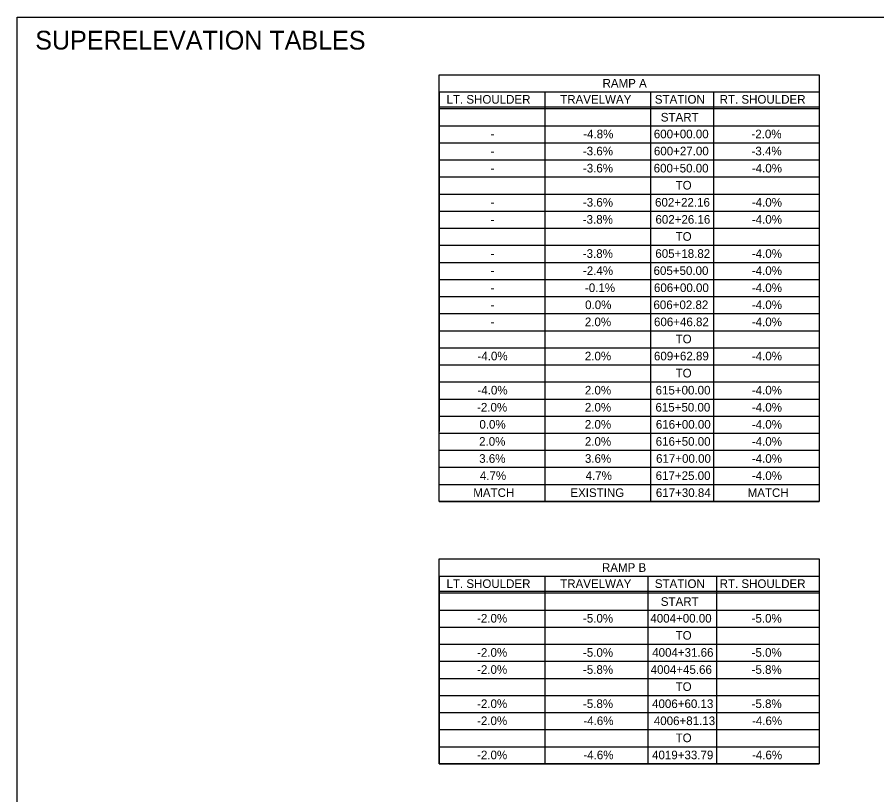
# Model space of a CAD drawing. Extents: x -15319374 to 1762012, y 465773 to 3693661.
# Drawn here: x -15314464.4 to -15314165.5, y 3691582.5 to 3691853 of the extents above; entities that cross this region are included whole.
import ezdxf

# ---------------------------------------------------------------- set-up
doc = ezdxf.new("R2010")
doc.units = 0
doc.layers.add('BORDER', color=7, linetype='Continuous')
doc.layers.add('DIMENSIONS', color=7, linetype='Continuous')

msp = doc.modelspace()

# ---------------------------------------------------------------- linework, layer by layer
at = {"layer": 'BORDER'}
for p, q in [((-15314317.7, 3691827.08), (-15314317.7, 3691708.88)), ((-15314280.93, 3691827.08), (-15314280.93, 3691702.35)), ((-15314244.16, 3691827.08), (-15314244.16, 3691702.35)), ((-15314222.29, 3691827.08), (-15314222.29, 3691702.35)), ((-15314185.52, 3691827.08), (-15314185.52, 3691702.35)), ((-15314317.7, 3691821.8), (-15314185.52, 3691821.8)), ((-15314317.7, 3691821.2), (-15314185.52, 3691821.2)), ((-15314317.7, 3691815.26), (-15314185.52, 3691815.26)), ((-15314317.7, 3691815.26), (-15314185.52, 3691815.26)), ((-15314317.7, 3691815.26), (-15314185.52, 3691815.26)), ((-15314317.7, 3691809.32), (-15314185.52, 3691809.32)), ((-15314317.7, 3691803.38), (-15314185.52, 3691803.38)), ((-15314317.7, 3691797.43), (-15314185.52, 3691797.43)), ((-15314317.7, 3691791.49), (-15314185.52, 3691791.49)), ((-15314317.7, 3691785.55), (-15314185.52, 3691785.55)), ((-15314317.7, 3691779.61), (-15314185.52, 3691779.61)), ((-15314317.7, 3691773.66), (-15314185.52, 3691773.66)), ((-15314317.7, 3691767.72), (-15314185.52, 3691767.72)), ((-15314317.7, 3691761.78), (-15314185.52, 3691761.78)), ((-15314317.7, 3691755.83), (-15314185.52, 3691755.83)), ((-15314317.7, 3691749.89), (-15314185.52, 3691749.89)), ((-15314317.7, 3691743.95), (-15314185.52, 3691743.95)), ((-15314317.7, 3691738.01), (-15314185.52, 3691738.01)), ((-15314317.7, 3691732.06), (-15314185.52, 3691732.06)), ((-15314317.7, 3691726.12), (-15314185.52, 3691726.12)), ((-15314317.7, 3691720.18), (-15314185.52, 3691720.18)), ((-15314317.7, 3691714.24), (-15314185.52, 3691714.24)), ((-15314317.7, 3691708.29), (-15314185.52, 3691708.29)), ((-15314317.7, 3691702.35), (-15314185.52, 3691702.35)), ((-15314280.93, 3691702.35), (-15314280.93, 3691684.52)), ((-15314244.16, 3691702.35), (-15314244.16, 3691684.52)), ((-15314222.29, 3691702.35), (-15314222.29, 3691684.52)), ((-15314317.7, 3691696.41), (-15314185.52, 3691696.41)), ((-15314317.7, 3691690.46), (-15314185.52, 3691690.46)), ((-15314317.7, 3691684.52), (-15314185.52, 3691684.52)), ((-15314317.7, 3691658.58), (-15314317.7, 3691593.28)), ((-15314280.93, 3691658.58), (-15314280.93, 3691593.28)), ((-15314245.16, 3691658.58), (-15314245.16, 3691593.28)), ((-15314221.29, 3691658.58), (-15314221.29, 3691593.28)), ((-15314185.52, 3691658.58), (-15314185.52, 3691593.28)), ((-15314317.7, 3691653.3), (-15314185.52, 3691653.3)), ((-15314317.7, 3691652.7), (-15314185.52, 3691652.7)), ((-15314317.7, 3691646.76), (-15314185.52, 3691646.76)), ((-15314317.7, 3691646.76), (-15314185.52, 3691646.76)), ((-15314317.7, 3691646.76), (-15314185.52, 3691646.76)), ((-15314317.7, 3691640.82), (-15314185.52, 3691640.82)), ((-15314317.7, 3691634.87), (-15314185.52, 3691634.87)), ((-15314317.7, 3691628.93), (-15314185.52, 3691628.93)), ((-15314317.7, 3691622.99), (-15314185.52, 3691622.99)), ((-15314317.7, 3691617.05), (-15314185.52, 3691617.05)), ((-15314317.7, 3691611.1), (-15314185.52, 3691611.1)), ((-15314317.7, 3691605.16), (-15314185.52, 3691605.16)), ((-15314317.7, 3691599.22), (-15314185.52, 3691599.22)), ((-15314317.7, 3691593.28), (-15314185.52, 3691593.28))]:
    msp.add_line(p, q, dxfattribs=at)
for points in [[(-15314464.43, 3691853.02), (-15313664.43, 3691853.02), (-15313664.43, 3691328.02), (-15314464.43, 3691328.02)], [(-15314317.7, 3691827.08), (-15314185.52, 3691827.08), (-15314185.52, 3691684.52), (-15314317.7, 3691684.52)], [(-15314317.7, 3691658.58), (-15314185.52, 3691658.58), (-15314185.52, 3691593.28), (-15314317.7, 3691593.28)]]:
    msp.add_lwpolyline(points, close=True, dxfattribs=at)
for points in [[(-15314317.7, 3691827.08), (-15314317.7, 3691833.02), (-15314185.52, 3691833.02), (-15314185.52, 3691827.08)], [(-15314317.7, 3691658.58), (-15314317.7, 3691664.52), (-15314185.52, 3691664.52), (-15314185.52, 3691658.58)]]:
    msp.add_lwpolyline(points, dxfattribs=at)

# ---------------------------------------------------------------- texts
msp.add_text('SUPERELEVATION TABLES', height=6.5214, rotation=360, dxfattribs=at).set_placement((-15314458.15, 3691841.76))
at = {"layer": 'DIMENSIONS'}
for s, p in [('RAMP A', (-15314260.88, 3691828.55)), ('LT. SHOULDER', (-15314315.14, 3691822.94)), ('TRAVELWAY', (-15314275.61, 3691822.94)), ('STATION', (-15314242.7, 3691822.94)), ('RT. SHOULDER', (-15314220.16, 3691822.94)), ('START', (-15314240.62, 3691816.72)), ('-', (-15314299.82, 3691810.89)), ('-4.8%', (-15314267.6, 3691810.89)), ('600+00.00', (-15314243.05, 3691810.89)), ('-2.0%', (-15314209.1, 3691810.89)), ('-', (-15314299.82, 3691804.95)), ('-3.6%', (-15314267.72, 3691804.95)), ('600+27.00', (-15314243.02, 3691804.95)), ('-3.4%', (-15314209.07, 3691804.95)), ('-', (-15314299.82, 3691799)), ('-3.6%', (-15314267.72, 3691799)), ('600+50.00', (-15314243.1, 3691799)), ('-4.0%', (-15314208.96, 3691799)), ('TO', (-15314235.47, 3691793.06)), ('-', (-15314299.82, 3691787.12)), ('-3.6%', (-15314267.72, 3691787.12)), ('602+22.16', (-15314242.62, 3691787.12)), ('-4.0%', (-15314208.96, 3691787.12)), ('-', (-15314299.82, 3691781.17)), ('-3.8%', (-15314267.76, 3691781.17)), ('602+26.16', (-15314242.48, 3691781.17)), ('-4.0%', (-15314208.96, 3691781.17)), ('TO', (-15314235.47, 3691775.23)), ('-', (-15314299.82, 3691769.29)), ('-3.8%', (-15314267.76, 3691769.29)), ('605+18.82', (-15314242.52, 3691769.29)), ('-4.0%', (-15314208.96, 3691769.29)), ('-', (-15314299.82, 3691763.35)), ('-2.4%', (-15314267.69, 3691763.35)), ('605+50.00', (-15314243.14, 3691763.35)), ('-4.0%', (-15314208.96, 3691763.35)), ('-', (-15314299.82, 3691757.4)), ('-0.1%', (-15314266.99, 3691757.4)), ('606+00.00', (-15314243, 3691757.4)), ('-4.0%', (-15314208.96, 3691757.4)), ('-', (-15314299.82, 3691751.46)), ('0.0%', (-15314266.94, 3691751.46)), ('606+02.82', (-15314243.18, 3691751.46)), ('-4.0%', (-15314208.96, 3691751.46)), ('-', (-15314299.82, 3691745.52)), ('2.0%', (-15314267.03, 3691745.52)), ('606+46.82', (-15314242.99, 3691745.52)), ('-4.0%', (-15314208.96, 3691745.52)), ('TO', (-15314235.47, 3691739.58)), ('-4.0%', (-15314304.37, 3691733.63)), ('2.0%', (-15314267.03, 3691733.63)), ('609+62.89', (-15314243, 3691733.63)), ('-4.0%', (-15314208.96, 3691733.63)), ('TO', (-15314235.47, 3691727.69)), ('-4.0%', (-15314304.37, 3691721.75)), ('2.0%', (-15314267.03, 3691721.75)), ('615+00.00', (-15314242.43, 3691721.75)), ('-4.0%', (-15314208.96, 3691721.75)), ('-2.0%', (-15314304.51, 3691715.81)), ('2.0%', (-15314267.03, 3691715.81)), ('615+50.00', (-15314242.48, 3691715.81)), ('-4.0%', (-15314208.96, 3691715.81)), ('0.0%', (-15314303.71, 3691709.86)), ('2.0%', (-15314267.03, 3691709.86)), ('616+00.00', (-15314242.34, 3691709.86)), ('-4.0%', (-15314208.96, 3691709.86)), ('2.0%', (-15314303.8, 3691703.92)), ('2.0%', (-15314267.03, 3691703.92)), ('616+50.00', (-15314242.39, 3691703.92)), ('-4.0%', (-15314208.96, 3691703.92)), ('3.6%', (-15314303.78, 3691697.98)), ('3.6%', (-15314267.01, 3691697.98)), ('617+00.00', (-15314242.27, 3691697.98)), ('-4.0%', (-15314208.96, 3691697.98)), ('4.7%', (-15314303.54, 3691692.03)), ('4.7%', (-15314266.77, 3691692.03)), ('617+25.00', (-15314242.41, 3691692.03)), ('-4.0%', (-15314208.96, 3691692.03)), ('MATCH', (-15314305.84, 3691686.09)), ('EXISTING', (-15314272.07, 3691686.09)), ('617+30.84', (-15314242.34, 3691686.09)), ('MATCH', (-15314210.43, 3691686.09)), ('RAMP B', (-15314261.08, 3691660.05)), ('LT. SHOULDER', (-15314315.14, 3691654.44)), ('TRAVELWAY', (-15314275.61, 3691654.44)), ('STATION', (-15314242.7, 3691654.44)), ('RT. SHOULDER', (-15314220.16, 3691654.44)), ('START', (-15314240.62, 3691648.21)), ('-2.0%', (-15314304.51, 3691642.39)), ('-5.0%', (-15314267.69, 3691642.39)), ('4004+00.00', (-15314244.25, 3691642.39)), ('-5.0%', (-15314209.05, 3691642.39)), ('TO', (-15314235.47, 3691636.44)), ('-2.0%', (-15314304.51, 3691630.5)), ('-5.0%', (-15314267.69, 3691630.5)), ('4004+31.66', (-15314243.61, 3691630.5)), ('-5.0%', (-15314209.05, 3691630.5)), ('-2.0%', (-15314304.51, 3691624.56)), ('-5.8%', (-15314267.69, 3691624.56)), ('4004+45.66', (-15314244.16, 3691624.56)), ('-5.8%', (-15314209.05, 3691624.56)), ('TO', (-15314235.47, 3691618.62)), ('-2.0%', (-15314304.51, 3691612.67)), ('-5.8%', (-15314267.69, 3691612.67)), ('4006+60.13', (-15314243.65, 3691612.67)), ('-5.8%', (-15314209.05, 3691612.67)), ('-2.0%', (-15314304.51, 3691606.73)), ('-4.6%', (-15314267.55, 3691606.73)), ('4006+81.13', (-15314243.04, 3691606.73)), ('-4.6%', (-15314208.91, 3691606.73)), ('TO', (-15314235.47, 3691600.79)), ('-2.0%', (-15314304.51, 3691594.84)), ('-4.6%', (-15314267.55, 3691594.84)), ('4019+33.79', (-15314243.66, 3691594.84)), ('-4.6%', (-15314208.91, 3691594.84))]:
    msp.add_text(s, height=3, dxfattribs=at).set_placement(p)

doc.saveas('drawing.dxf')
